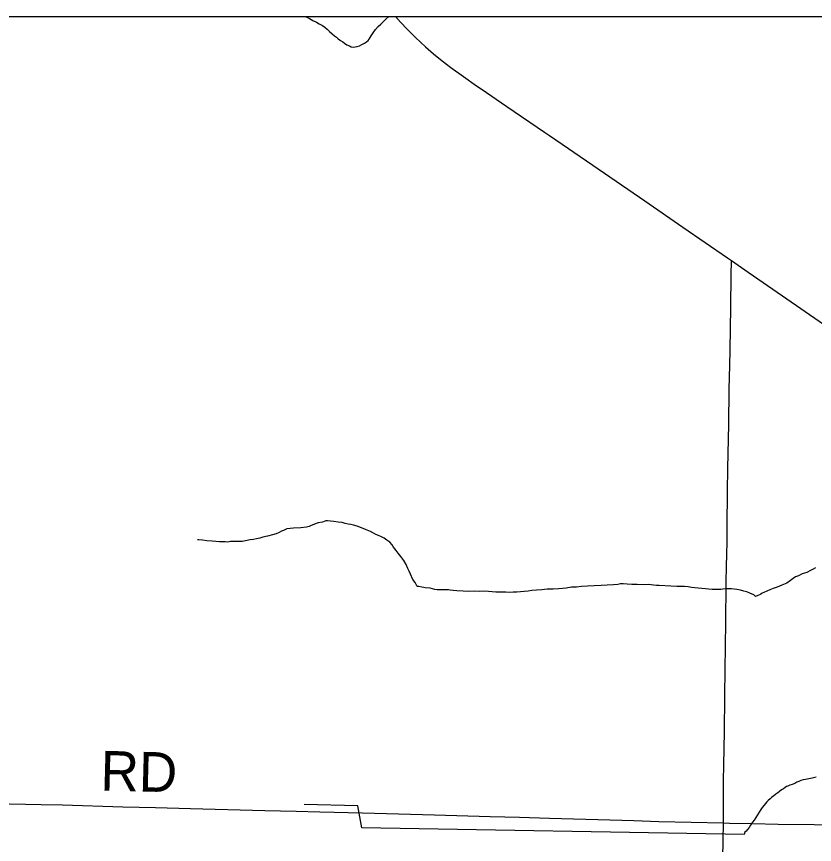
# Model space of a CAD drawing. Extents: x 2.1 to 73.9, y 4 to 26.
# Drawn here: x 46.678 to 47.249, y 24.313 to 24.905 of the extents above; entities that cross this region are included whole.
import ezdxf

# ---------------------------------------------------------------- set-up
doc = ezdxf.new("R2010")
doc.units = 0
for name, color, linetype in [('GM_X_County_Road', 7, 'Continuous'), ('GM_X_County_Road_Text', 7, 'Continuous'), ('GM_X_Minor_River', 7, 'Continuous'), ('GM_X_State_Route', 7, 'Continuous'), ('GM_X_Township_Road', 7, 'Continuous'), ('SH_Data', 7, 'Continuous')]:
    doc.layers.add(name, color=color, linetype=linetype)

msp = doc.modelspace()

# ---------------------------------------------------------------- linework, layer by layer
at = {"layer": 'GM_X_County_Road'}
for points in [[(46.66149, 24.34208), (46.69573, 24.34133), (46.71095, 24.34095), (46.75414, 24.33969), (46.77745, 24.33909), (46.80262, 24.33845), (46.85576, 24.337), (46.87813, 24.33648), (46.89523, 24.33607), (46.92568, 24.33531), (46.95147, 24.33463), (46.97726, 24.33393), (47.01703, 24.33275), (47.03816, 24.33213), (47.0596, 24.33155), (47.10279, 24.33023), (47.11987, 24.3297), (47.1379, 24.32917), (47.18405, 24.32808)], [(47.18405, 24.32808), (47.18855, 24.32797), (47.20503, 24.32761), (47.22337, 24.32729), (47.24916, 24.32685), (47.28149, 24.32632)]]:
    msp.add_lwpolyline(points, dxfattribs=at)
at = {"layer": 'GM_X_Minor_River'}
for points in [[(46.88518, 24.90511), (46.88536, 24.90501), (46.8878, 24.90362), (46.89023, 24.90223), (46.89267, 24.90103), (46.89473, 24.90002), (46.89717, 24.89863), (46.89866, 24.89745), (46.90033, 24.89608), (46.902, 24.89433), (46.90386, 24.89276), (46.90553, 24.89139), (46.90703, 24.8904), (46.90833, 24.88923), (46.91001, 24.88805), (46.9115, 24.88706), (46.91281, 24.88608), (46.91449, 24.8849), (46.91637, 24.88409), (46.91768, 24.88348), (46.919, 24.88326), (46.92034, 24.88342), (46.92186, 24.88376), (46.92359, 24.88428), (46.92532, 24.88519)], [(46.92532, 24.88519), (46.92705, 24.88609), (46.92859, 24.88701), (46.92976, 24.88793), (46.93054, 24.88905), (46.93193, 24.89129), (46.93332, 24.89353), (46.93489, 24.89577), (46.93685, 24.898), (46.93879, 24.89966), (46.94054, 24.90132), (46.94229, 24.90318), (46.94451, 24.90511)], [(46.8855, 24.5398), (46.8815, 24.53933), (46.87636, 24.53889), (46.87161, 24.53863), (46.86911, 24.53737), (46.86776, 24.53683), (46.86603, 24.53593), (46.86392, 24.53503), (46.86124, 24.53415), (46.85761, 24.53329), (46.85436, 24.53261), (46.85207, 24.53191), (46.84978, 24.5314), (46.84767, 24.53089), (46.8452, 24.53057), (46.84195, 24.52989), (46.83947, 24.52958), (46.83719, 24.52944), (46.83491, 24.5295), (46.83301, 24.52955), (46.8313, 24.5294), (46.82921, 24.52908), (46.82731, 24.52912), (46.8256, 24.52917), (46.82332, 24.52923), (46.82067, 24.52948), (46.81802, 24.52974), (46.81422, 24.53003), (46.8112, 24.53048), (46.80854, 24.53055), (46.80759, 24.53058), (46.80759, 24.53058)], [(47.14654, 24.49744), (47.1382, 24.49804), (47.1363, 24.49808), (47.13403, 24.49833), (47.1308, 24.4986), (47.12681, 24.49852), (47.12245, 24.49863), (47.11846, 24.49873), (47.11524, 24.499), (47.1124, 24.49926), (47.11049, 24.49912), (47.10859, 24.49879), (47.10535, 24.49849), (47.10098, 24.49823), (47.0966, 24.49796), (47.09166, 24.4977), (47.08671, 24.49745), (47.08253, 24.49718), (47.07891, 24.49689), (47.0753, 24.49679), (47.07148, 24.49613), (47.06635, 24.49569), (47.06216, 24.49542), (47.05798, 24.49534), (47.05398, 24.49487), (47.05036, 24.49458), (47.04694, 24.49429), (47.04427, 24.49398), (47.04141, 24.49367), (47.03875, 24.49355), (47.03608, 24.49323), (47.03362, 24.4933), (47.03076, 24.49299), (47.0283, 24.49324), (47.02601, 24.49311), (47.02355, 24.49318), (47.02108, 24.49324), (47.01862, 24.49349), (47.01596, 24.49375), (47.01293, 24.49382), (47.00951, 24.49372), (47.00571, 24.49382), (47.00172, 24.49373), (46.99773, 24.49383), (46.99318, 24.49414), (46.99053, 24.4944), (46.98845, 24.49464), (46.98731, 24.49486), (46.98447, 24.49493), (46.98314, 24.49496), (46.9818, 24.49481), (46.98029, 24.49485), (46.97915, 24.49488), (46.97744, 24.49511), (46.97405, 24.49596), (46.97064, 24.49642), (46.96969, 24.49645), (46.96818, 24.49686), (46.96591, 24.4973), (46.96477, 24.49733), (46.96333, 24.50022), (46.96167, 24.50235), (46.96006, 24.50619), (46.95916, 24.5083), (46.95807, 24.51023), (46.957, 24.51291), (46.95537, 24.51599), (46.95316, 24.51871), (46.95132, 24.52103), (46.94985, 24.52297), (46.94874, 24.52433), (46.94782, 24.52549), (46.94691, 24.52703), (46.94525, 24.52897), (46.9432, 24.53054), (46.94114, 24.53193), (46.93927, 24.53292), (46.9372, 24.53373), (46.93532, 24.53454), (46.93363, 24.53535), (46.93138, 24.53654), (46.92781, 24.53796), (46.925, 24.53936), (46.92198, 24.54039), (46.91916, 24.54122), (46.91727, 24.54165), (46.91537, 24.54189), (46.9133, 24.54232), (46.91103, 24.54295), (46.90819, 24.5434), (46.90516, 24.54367), (46.9027, 24.54392), (46.90062, 24.54416), (46.89948, 24.54419), (46.89699, 24.5433), (46.89394, 24.54281), (46.89259, 24.54228), (46.89087, 24.54156), (46.88895, 24.54085), (46.88742, 24.54032), (46.8855, 24.5398)], [(47.25, 24.51056), (47.24827, 24.50966), (47.24635, 24.50876), (47.24384, 24.5073), (47.2404, 24.50625), (47.2379, 24.50498), (47.23578, 24.50409), (47.23405, 24.50299), (47.23211, 24.50152), (47.22941, 24.4997), (47.22595, 24.49826), (47.22269, 24.49683), (47.21981, 24.49576), (47.21732, 24.49488), (47.21521, 24.49398), (47.21291, 24.49309), (47.21194, 24.49255), (47.21098, 24.49181), (47.20982, 24.49127), (47.20867, 24.49073), (47.20695, 24.4902), (47.20583, 24.49137), (47.20301, 24.49239), (47.20076, 24.4934), (47.19868, 24.49402), (47.19623, 24.49466), (47.19377, 24.4951), (47.19188, 24.49534), (47.18999, 24.49557), (47.1879, 24.49563), (47.18581, 24.49549), (47.18371, 24.49536), (47.18219, 24.4952), (47.17877, 24.4951), (47.17592, 24.49517), (47.17345, 24.49524), (47.17118, 24.49548), (47.16872, 24.49574), (47.16607, 24.49599), (47.1636, 24.49625), (47.16133, 24.4965), (47.15887, 24.49694), (47.15622, 24.4972), (47.15375, 24.49726), (47.15072, 24.49734), (47.14654, 24.49744)], [(47.25041, 24.36073), (47.24774, 24.36004), (47.24526, 24.35972), (47.24297, 24.35921), (47.24125, 24.35888), (47.23953, 24.35835), (47.23818, 24.35782), (47.23665, 24.35729), (47.2353, 24.35637), (47.23338, 24.35566), (47.23166, 24.35514), (47.23031, 24.35441), (47.22935, 24.35405)], [(47.22935, 24.35405), (47.22838, 24.35332), (47.22704, 24.35259), (47.22568, 24.35168), (47.22433, 24.35058), (47.22297, 24.34966), (47.22162, 24.34856), (47.22007, 24.34746), (47.21852, 24.34636), (47.21754, 24.34524), (47.21619, 24.34414), (47.21521, 24.34321), (47.21423, 24.34191), (47.21325, 24.34079), (47.21188, 24.33912), (47.21089, 24.33763), (47.20971, 24.33576), (47.20614, 24.32996), (47.20497, 24.32866), (47.20418, 24.32755), (47.20358, 24.32642), (47.20259, 24.32474), (47.20142, 24.32344), (47.20044, 24.32213), (47.19947, 24.3214), (47.19893, 24.31991)], [(47.19893, 24.31991), (46.9251, 24.32459), (46.92227, 24.34043), (46.88392, 24.34121)]]:
    msp.add_lwpolyline(points, dxfattribs=at)
at = {"layer": 'GM_X_State_Route'}
for points in [[(46.94926, 24.90511), (46.95279, 24.9012), (46.95774, 24.89603), (46.96373, 24.89013), (46.97079, 24.88355), (46.97661, 24.87839), (46.98265, 24.87347), (46.98883, 24.86873), (46.99792, 24.86217), (47.00742, 24.85564)], [(47.00742, 24.85564), (47.01073, 24.85336), (47.02891, 24.84085), (47.05604, 24.82233)], [(47.05604, 24.82233), (47.05946, 24.82), (47.09049, 24.79874), (47.12772, 24.77333), (47.15514, 24.7545), (47.18694, 24.73246), (47.18979, 24.73049), (47.20177, 24.72229), (47.22629, 24.70528), (47.25568, 24.68494)]]:
    msp.add_lwpolyline(points, dxfattribs=at)
at = {"layer": 'GM_X_Township_Road'}
for points in [[(47.18638, 24.51389), (47.18643, 24.5179), (47.1867, 24.53126), (47.1868, 24.54028), (47.18708, 24.56514), (47.18732, 24.58192), (47.18787, 24.61331), (47.18824, 24.63818), (47.18861, 24.65558), (47.18883, 24.66646), (47.18941, 24.69722), (47.18972, 24.71973), (47.18979, 24.73049)], [(47.18405, 24.32808), (47.18411, 24.33764), (47.18427, 24.35816), (47.18437, 24.36965), (47.18475, 24.39328), (47.18504, 24.41845), (47.18534, 24.43803), (47.18548, 24.45388), (47.18585, 24.47253), (47.18618, 24.49832), (47.18638, 24.51389)], [(47.17138, 23.82458), (47.17174, 23.83956), (47.17214, 23.85199), (47.17378, 23.90947), (47.17478, 23.94675), (47.17587, 23.98963), (47.17615, 24.00237), (47.17713, 24.04308), (47.17751, 24.05954), (47.178, 24.07881), (47.17889, 24.10646), (47.17952, 24.12572), (47.18066, 24.16611), (47.18119, 24.18973), (47.18142, 24.19936), (47.18206, 24.2239), (47.1826, 24.24783), (47.1836, 24.30284), (47.18405, 24.32808)]]:
    msp.add_lwpolyline(points, dxfattribs=at)
at = {"layer": 'SH_Data'}
msp.add_line((41.95853, 24.90511), (48.75853, 24.90511), dxfattribs=at)

# ---------------------------------------------------------------- texts
at = {"layer": 'GM_X_County_Road_Text'}
msp.add_text('RD', height=0.028409, rotation=358.52369, dxfattribs=at).set_placement((46.73784, 24.35135))

doc.saveas('drawing.dxf')
